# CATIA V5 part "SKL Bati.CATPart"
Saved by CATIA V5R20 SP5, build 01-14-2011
Part number: SKL Bati
Publications: "Plan.1", "Point.1", "Droite.1", "Plan.2", "Droite.2"
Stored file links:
  G:\IAO Final\SKL Bati.CATPart
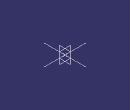
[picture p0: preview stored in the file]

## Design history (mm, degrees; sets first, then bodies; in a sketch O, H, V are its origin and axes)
Body1 (main body)
  Plane1: type Offset, RefPlane yz-plane, Offset 0
  Point1: (0, 0, 0)
  Line1: type Normal, RefPoint Point1, RefSkin Plane1, Start 0, End 20
  Plane2: type Offset, RefPlane zx-plane, Offset 0
  Line2: type Normal, RefPoint Point1, RefSkin Plane2, Start 0, End 20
